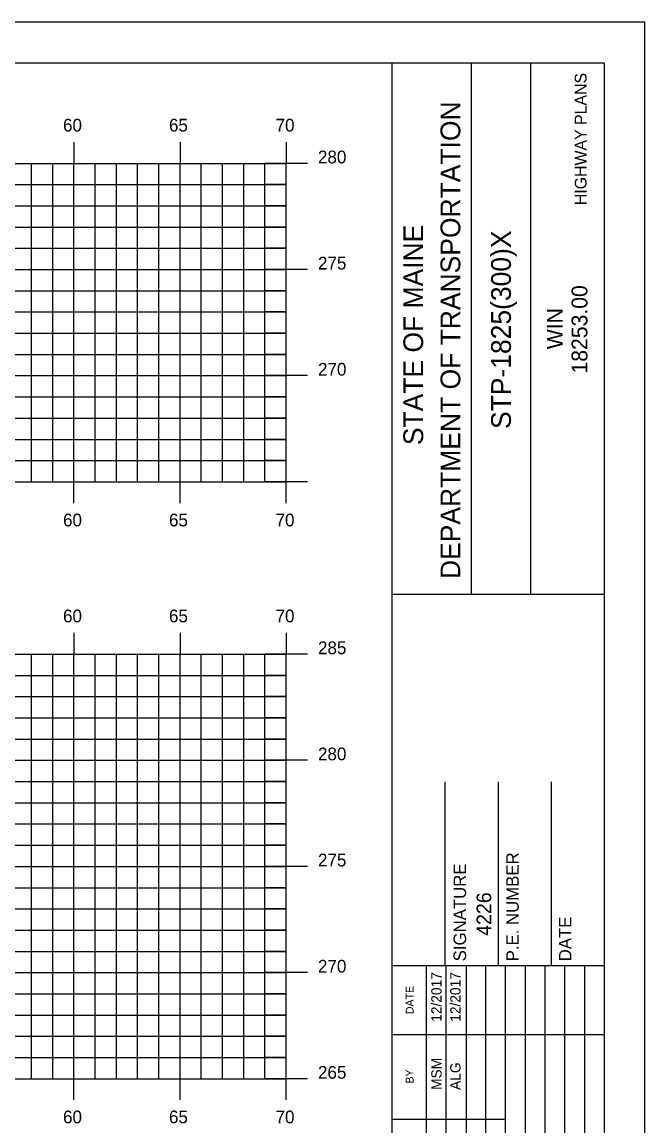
# Model space of a CAD drawing. Extents: x 854453 to 854623, y 366268 to 366378.
# Drawn here: x 854594 to 854623.3, y 366326.2 to 366378.2 of the extents above; entities that cross this region are included whole.
import ezdxf

# ---------------------------------------------------------------- set-up
doc = ezdxf.new("R2010")
doc.units = 0
for name, color, linetype in [('ANNOTATION', 7, 'Continuous'), ('BORDER', 7, 'Continuous'), ('H_V ANNOTATION', 7, 'Continuous'), ('HIGHWAY_TITLE', 7, 'Continuous'), ('MAJOR', 7, 'Continuous'), ('MINOR', 7, 'Continuous'), ('PLOT BOUNDARY', 7, 'Continuous')]:
    doc.layers.add(name, color=color, linetype=linetype)

msp = doc.modelspace()

# ---------------------------------------------------------------- linework, layer by layer
at = {"layer": 'BORDER'}
for p, q in [((854621.439, 366376.236), (854461.439, 366376.236)), ((854611.439, 366271.236), (854611.439, 366376.239)), ((854615.167, 366351.234), (854615.167, 366376.234)), ((854617.962, 366351.234), (854617.962, 366376.234)), ((854621.439, 366271.236), (854621.439, 366376.236)), ((854611.44, 366351.231), (854621.439, 366351.231)), ((854613.939, 366333.739), (854613.939, 366342.387)), ((854616.439, 366333.739), (854616.439, 366342.387)), ((854618.939, 366333.739), (854618.939, 366342.387)), ((854611.439, 366333.739), (854621.439, 366333.739))]:
    msp.add_line(p, q, dxfattribs=at)
for points in [[(854613.054, 366330.489), (854613.054, 366333.739)], [(854613.986, 366316.242), (854613.986, 366333.739)], [(854614.918, 366333.739), (854614.918, 366316.242)], [(854615.85, 366316.242), (854615.85, 366333.739)], [(854616.781, 366316.242), (854616.781, 366333.739)], [(854617.713, 366316.242), (854617.713, 366333.739)], [(854618.645, 366316.242), (854618.645, 366333.739)], [(854619.576, 366316.242), (854619.576, 366333.739)], [(854620.508, 366316.242), (854620.508, 366333.739)], [(854613.055, 366316.242), (854613.055, 366333.033)], [(854611.439, 366330.489), (854621.439, 366330.489)], [(854611.439, 366326.489), (854613.055, 366326.489)], [(854613.054, 366326.489), (854616.78, 366326.489)]]:
    msp.add_lwpolyline(points, dxfattribs=at)
at = {"layer": 'MAJOR'}
for p, q in [((854596.439, 366372.523), (854596.439, 366371.521)), ((854601.439, 366372.523), (854601.439, 366371.521)), ((854606.439, 366372.523), (854606.439, 366371.521)), ((854466.439, 366371.521), (854606.439, 366371.521)), ((854596.439, 366356.521), (854596.439, 366371.521)), ((854601.439, 366356.521), (854601.439, 366371.521)), ((854607.441, 366371.521), (854605.437, 366371.521)), ((854606.439, 366356.521), (854606.439, 366371.521)), ((854606.439, 366356.521), (854606.439, 366371.521)), ((854466.439, 366366.521), (854606.439, 366366.521)), ((854607.441, 366366.521), (854605.437, 366366.521)), ((854466.439, 366361.521), (854606.439, 366361.521)), ((854607.441, 366361.521), (854605.437, 366361.521)), ((854466.439, 366356.521), (854606.439, 366356.521)), ((854466.439, 366356.521), (854606.439, 366356.521)), ((854596.439, 366355.519), (854596.439, 366356.521)), ((854601.439, 366355.519), (854601.439, 366356.521)), ((854607.441, 366356.521), (854605.437, 366356.521)), ((854606.439, 366355.519), (854606.439, 366356.521)), ((854596.439, 366349.403), (854596.439, 366348.401)), ((854601.439, 366349.403), (854601.439, 366348.401)), ((854606.439, 366349.403), (854606.439, 366348.401)), ((854466.439, 366348.401), (854606.439, 366348.401)), ((854466.439, 366348.401), (854606.439, 366348.401)), ((854596.439, 366328.401), (854596.439, 366348.401)), ((854601.439, 366328.401), (854601.439, 366348.401)), ((854607.441, 366348.401), (854605.437, 366348.401)), ((854606.439, 366328.401), (854606.439, 366348.401)), ((854606.439, 366328.401), (854606.439, 366348.401)), ((854466.439, 366343.401), (854606.439, 366343.401)), ((854607.441, 366343.401), (854605.437, 366343.401)), ((854466.439, 366338.401), (854606.439, 366338.401)), ((854607.441, 366338.401), (854605.437, 366338.401)), ((854466.439, 366333.401), (854606.439, 366333.401)), ((854607.441, 366333.401), (854605.437, 366333.401)), ((854466.439, 366328.401), (854606.439, 366328.401)), ((854466.439, 366328.401), (854606.439, 366328.401)), ((854596.439, 366327.399), (854596.439, 366328.401)), ((854601.439, 366327.399), (854601.439, 366328.401)), ((854607.441, 366328.401), (854605.437, 366328.401)), ((854606.439, 366327.399), (854606.439, 366328.401))]:
    msp.add_line(p, q, dxfattribs=at)
at = {"layer": 'MINOR'}
for p, q in [((854594.439, 366356.521), (854594.439, 366371.521)), ((854595.439, 366356.521), (854595.439, 366371.521)), ((854597.439, 366356.521), (854597.439, 366371.521)), ((854598.439, 366356.521), (854598.439, 366371.521)), ((854599.439, 366356.521), (854599.439, 366371.521)), ((854600.439, 366356.521), (854600.439, 366371.521)), ((854602.439, 366356.521), (854602.439, 366371.521)), ((854603.439, 366356.521), (854603.439, 366371.521)), ((854604.439, 366356.521), (854604.439, 366371.521)), ((854605.439, 366356.521), (854605.439, 366371.521)), ((854466.439, 366370.521), (854606.439, 366370.521)), ((854606.439, 366370.521), (854605.437, 366370.521)), ((854466.439, 366369.521), (854606.439, 366369.521)), ((854606.439, 366369.521), (854605.437, 366369.521)), ((854466.439, 366368.521), (854606.439, 366368.521)), ((854606.439, 366368.521), (854605.437, 366368.521)), ((854466.439, 366367.521), (854606.439, 366367.521)), ((854606.439, 366367.521), (854605.437, 366367.521)), ((854466.439, 366365.521), (854606.439, 366365.521)), ((854606.439, 366365.521), (854605.437, 366365.521)), ((854466.439, 366364.521), (854606.439, 366364.521)), ((854606.439, 366364.521), (854605.437, 366364.521)), ((854466.439, 366363.521), (854606.439, 366363.521)), ((854606.439, 366363.521), (854605.437, 366363.521)), ((854466.439, 366362.521), (854606.439, 366362.521)), ((854606.439, 366362.521), (854605.437, 366362.521)), ((854466.439, 366360.521), (854606.439, 366360.521)), ((854606.439, 366360.521), (854605.437, 366360.521)), ((854466.439, 366359.521), (854606.439, 366359.521)), ((854606.439, 366359.521), (854605.437, 366359.521)), ((854466.439, 366358.521), (854606.439, 366358.521)), ((854606.439, 366358.521), (854605.437, 366358.521)), ((854466.439, 366357.521), (854606.439, 366357.521)), ((854606.439, 366357.521), (854605.437, 366357.521)), ((854594.439, 366328.401), (854594.439, 366348.401)), ((854595.439, 366328.401), (854595.439, 366348.401)), ((854597.439, 366328.401), (854597.439, 366348.401)), ((854598.439, 366328.401), (854598.439, 366348.401)), ((854599.439, 366328.401), (854599.439, 366348.401)), ((854600.439, 366328.401), (854600.439, 366348.401)), ((854602.439, 366328.401), (854602.439, 366348.401)), ((854603.439, 366328.401), (854603.439, 366348.401)), ((854604.439, 366328.401), (854604.439, 366348.401)), ((854605.439, 366328.401), (854605.439, 366348.401)), ((854466.439, 366347.401), (854606.439, 366347.401)), ((854606.439, 366347.401), (854605.437, 366347.401)), ((854466.439, 366346.401), (854606.439, 366346.401)), ((854606.439, 366346.401), (854605.437, 366346.401)), ((854466.439, 366345.401), (854606.439, 366345.401)), ((854606.439, 366345.401), (854605.437, 366345.401)), ((854466.439, 366344.401), (854606.439, 366344.401)), ((854606.439, 366344.401), (854605.437, 366344.401)), ((854466.439, 366342.401), (854606.439, 366342.401)), ((854606.439, 366342.401), (854605.437, 366342.401)), ((854466.439, 366341.401), (854606.439, 366341.401)), ((854606.439, 366341.401), (854605.437, 366341.401)), ((854466.439, 366340.401), (854606.439, 366340.401)), ((854606.439, 366340.401), (854605.437, 366340.401)), ((854466.439, 366339.401), (854606.439, 366339.401)), ((854606.439, 366339.401), (854605.437, 366339.401)), ((854466.439, 366337.401), (854606.439, 366337.401)), ((854606.439, 366337.401), (854605.437, 366337.401)), ((854466.439, 366336.401), (854606.439, 366336.401)), ((854606.439, 366336.401), (854605.437, 366336.401)), ((854466.439, 366335.401), (854606.439, 366335.401)), ((854606.439, 366335.401), (854605.437, 366335.401)), ((854466.439, 366334.401), (854606.439, 366334.401)), ((854606.439, 366334.401), (854605.437, 366334.401)), ((854466.439, 366332.401), (854606.439, 366332.401)), ((854606.439, 366332.401), (854605.437, 366332.401)), ((854466.439, 366331.401), (854606.439, 366331.401)), ((854606.439, 366331.401), (854605.437, 366331.401)), ((854466.439, 366330.401), (854606.439, 366330.401)), ((854606.439, 366330.401), (854605.437, 366330.401)), ((854466.439, 366329.401), (854606.439, 366329.401)), ((854606.439, 366329.401), (854605.437, 366329.401))]:
    msp.add_line(p, q, dxfattribs=at)
at = {"layer": 'PLOT BOUNDARY'}
msp.add_lwpolyline([(854453.345, 366268.177), (854623.345, 366268.177), (854623.345, 366378.177), (854453.345, 366378.177)], close=True, dxfattribs=at)

# ---------------------------------------------------------------- texts
at = {"layer": 'ANNOTATION'}
msp.add_text('4226', height=0.69, rotation=90, dxfattribs=at).set_placement((854616.103, 366335.13))
at = {"layer": 'BORDER'}
for s, height, p in [('DEPARTMENT OF TRANSPORTATION', 0.93176, (854614.646, 366351.942)), ('STATE OF MAINE', 0.93176, (854612.894, 366358.248)), ('STP-1825(300)X', 0.93176, (854617.031, 366359.008)), ('18253.00', 0.7453, (854620.634, 366361.623)), ('WIN', 0.7453, (854619.476, 366362.766)), ('P.E. NUMBER', 0.59055, (854617.4, 366333.932)), ('SIGNATURE', 0.5906, (854614.919, 366333.932)), ('DATE', 0.5906, (854619.88, 366333.932)), ('12/2017', 0.4845, (854613.762, 366331.081)), ('12/2017', 0.4845, (854614.656, 366331.081)), ('DATE', 0.3714, (854612.443, 366331.445)), ('MSM', 0.4845, (854613.762, 366327.872)), ('ALG', 0.4845, (854614.656, 366327.872)), ('BY', 0.3714, (854612.443, 366328.174))]:
    msp.add_text(s, height=height, rotation=90, dxfattribs=at).set_placement(p)
at = {"layer": 'H_V ANNOTATION'}
for s, p in [('60', (854595.925, 366373.021)), ('65', (854600.917, 366373.021)), ('70', (854605.941, 366373.021)), ('280', (854607.939, 366371.521)), ('275', (854607.939, 366366.521)), ('270', (854607.939, 366361.521)), ('60', (854595.925, 366354.421)), ('65', (854600.917, 366354.421)), ('70', (854605.941, 366354.421)), ('60', (854595.925, 366349.901)), ('65', (854600.917, 366349.901)), ('70', (854605.941, 366349.901)), ('285', (854607.939, 366348.401)), ('280', (854607.939, 366343.401)), ('275', (854607.939, 366338.401)), ('270', (854607.939, 366333.401)), ('265', (854607.939, 366328.401)), ('60', (854595.925, 366326.301)), ('65', (854600.917, 366326.301)), ('70', (854605.941, 366326.301))]:
    msp.add_text(s, height=0.6, dxfattribs=at).set_placement(p)
at = {"layer": 'HIGHWAY_TITLE'}
msp.add_text('HIGHWAY PLANS', height=0.55901, rotation=90, dxfattribs=at).set_placement((854620.597, 366369.552))

doc.saveas('drawing.dxf')
